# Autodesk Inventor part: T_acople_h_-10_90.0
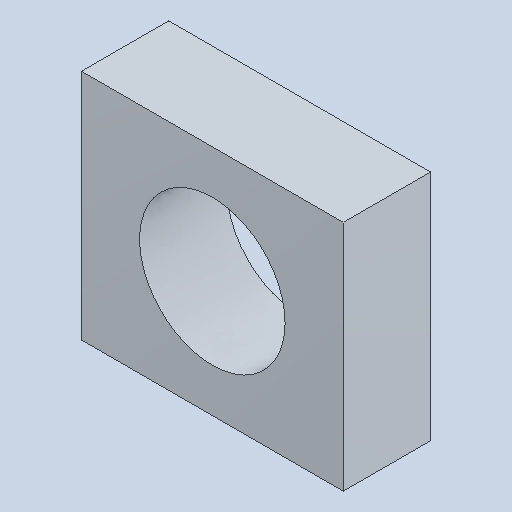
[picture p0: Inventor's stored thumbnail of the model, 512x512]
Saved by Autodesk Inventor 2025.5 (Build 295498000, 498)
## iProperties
Created: 2026-10
Part Number: T_acople_h_-10_90.0
Material: Genérico
Document SubType Name: Modeling
Designer: Luis M
Density: 1 g/cm^3
Appearance: Valor por defecto
Author: Luis M
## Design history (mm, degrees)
feature "Base1"
node "Sólido1"
